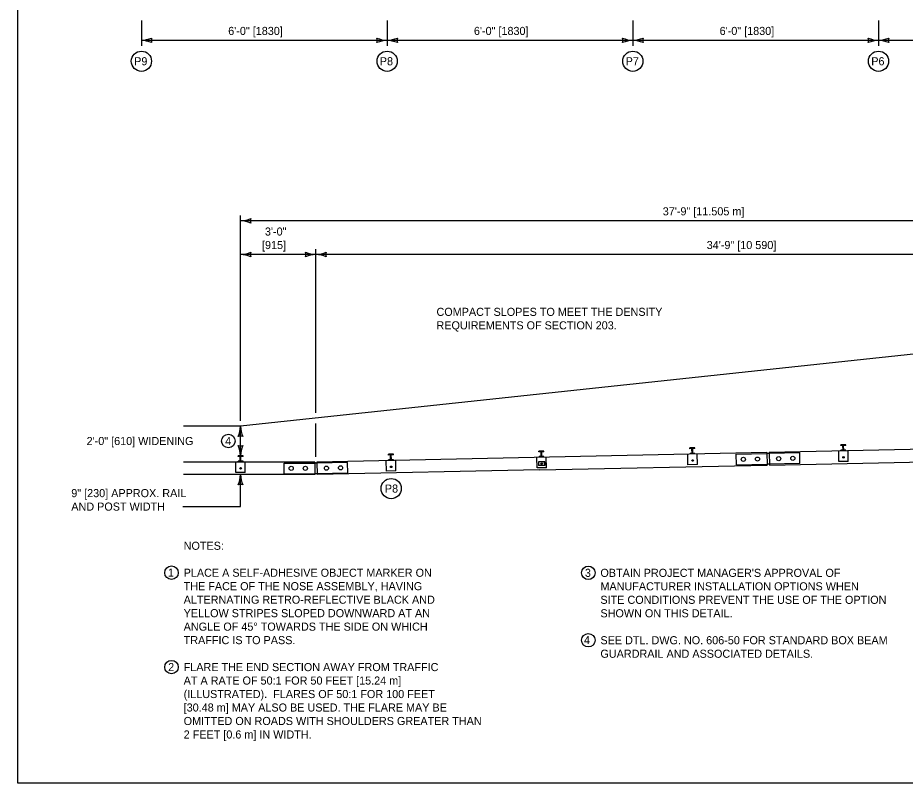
# Model space of a CAD drawing. Extents: x 49991.4 to 50021, y 49987.6 to 50011.4.
# Drawn here: x 49999.38 to 50005.97, y 49987.8 to 49993.48 of the extents above; entities that cross this region are included whole.
import ezdxf

# ---------------------------------------------------------------- set-up
doc = ezdxf.new("R2010")
doc.units = 0
for name, color, linetype in [('Level 1', 7, 'Continuous'), ('Level 2', 7, 'Continuous'), ('Level 3', 7, 'Continuous'), ('Level 4', 7, 'Continuous')]:
    doc.layers.add(name, color=color, linetype=linetype)

msp = doc.modelspace()

# ---------------------------------------------------------------- linework, layer by layer
at = {"layer": 'Level 1'}
for p, q in [((50008.0791, 49991.2004), (50001.0367, 49990.4473)), ((50001.0367, 49990.4473), (50000.6145, 49990.4473)), ((50004.4067, 49990.2872), (50004.3705, 49990.2864)), ((50004.3707, 49990.2808), (50004.3705, 49990.2864)), ((50004.386, 49990.2811), (50004.3707, 49990.2808)), ((50004.3867, 49990.2457), (50004.386, 49990.2811)), ((50004.4069, 49990.2816), (50004.3916, 49990.2812)), ((50004.3923, 49990.2458), (50004.3916, 49990.2812)), ((50004.4069, 49990.2816), (50004.4067, 49990.2872)), ((50008.3088, 49990.3226), (50004.9581, 49990.2521)), ((50005.5265, 49990.3107), (50005.4903, 49990.3099)), ((50005.4904, 49990.3043), (50005.4903, 49990.3099)), ((50005.5057, 49990.3047), (50005.4904, 49990.3043)), ((50005.5065, 49990.2693), (50005.5057, 49990.3047)), ((50005.5266, 49990.3051), (50005.5113, 49990.3048)), ((50005.5121, 49990.2694), (50005.5113, 49990.3048)), ((50005.5266, 49990.3051), (50005.5265, 49990.3107)), ((50001.0186, 49990.2226), (50001.0186, 49990.2283)), ((50001.0548, 49990.2283), (50001.0186, 49990.2283)), ((50001.0339, 49990.2226), (50001.0186, 49990.2226)), ((50001.0339, 49990.1873), (50001.0339, 49990.2226)), ((50001.0396, 49990.1873), (50001.0396, 49990.2226)), ((50001.0548, 49990.2226), (50001.0396, 49990.2226)), ((50001.0548, 49990.2226), (50001.0548, 49990.2283)), ((50004.9409, 49990.2518), (50001.6028, 49990.1816)), ((50002.1702, 49990.2403), (50002.1339, 49990.2395)), ((50002.1341, 49990.2338), (50002.1339, 49990.2395)), ((50002.1495, 49990.2341), (50002.1341, 49990.2338)), ((50002.1502, 49990.1988), (50002.1495, 49990.2341)), ((50002.1704, 49990.2346), (50002.1551, 49990.2342)), ((50002.1558, 49990.1989), (50002.1551, 49990.2342)), ((50002.1704, 49990.2346), (50002.1702, 49990.2403)), ((50003.2871, 49990.2636), (50003.2508, 49990.2629)), ((50003.2509, 49990.2573), (50003.2508, 49990.2629)), ((50003.2663, 49990.2576), (50003.2509, 49990.2573)), ((50003.267, 49990.2222), (50003.2516, 49990.2218)), ((50003.2518, 49990.2162), (50003.2516, 49990.2218)), ((50003.267, 49990.2222), (50003.2663, 49990.2576)), ((50003.2872, 49990.258), (50003.2718, 49990.2577)), ((50003.2725, 49990.2223), (50003.2718, 49990.2577)), ((50003.2879, 49990.2226), (50003.2725, 49990.2223)), ((50003.2872, 49990.258), (50003.2871, 49990.2636)), ((50003.288, 49990.217), (50003.2879, 49990.2226)), ((50004.3867, 49990.2457), (50004.3714, 49990.2454)), ((50004.3715, 49990.2398), (50004.3714, 49990.2454)), ((50004.4076, 49990.2462), (50004.3923, 49990.2458)), ((50004.4077, 49990.2405), (50004.4076, 49990.2462)), ((50004.9409, 49990.2517), (50004.9429, 49990.1587)), ((50004.9583, 49990.2453), (50004.941, 49990.2448)), ((50004.9581, 49990.2522), (50004.9601, 49990.159)), ((50005.5065, 49990.2693), (50005.4911, 49990.2689)), ((50005.4913, 49990.2633), (50005.4911, 49990.2689)), ((50005.5274, 49990.2697), (50005.5121, 49990.2694)), ((50005.5274, 49990.2641), (50005.5274, 49990.2697)), ((50001.5874, 49990.1817), (50000.6145, 49990.1817)), ((50001.0339, 49990.1873), (50001.0186, 49990.1873)), ((50001.0186, 49990.1817), (50001.0186, 49990.1873)), ((50001.0548, 49990.1873), (50001.0396, 49990.1873)), ((50001.0548, 49990.1817), (50001.0548, 49990.1873)), ((50001.5874, 49990.1816), (50001.5874, 49990.0885)), ((50001.6029, 49990.1747), (50001.5874, 49990.1747)), ((50001.6028, 49990.1816), (50001.6047, 49990.0884)), ((50002.1502, 49990.1988), (50002.1348, 49990.1985)), ((50002.1349, 49990.1929), (50002.1348, 49990.1985)), ((50002.171, 49990.1992), (50002.1558, 49990.1989)), ((50002.1712, 49990.1936), (50002.171, 49990.1992)), ((50003.2942, 49990.1843), (50003.2476, 49990.1833)), ((50003.2476, 49990.1833), (50003.2482, 49990.156)), ((50003.2947, 49990.157), (50003.2482, 49990.156)), ((50003.2903, 49990.1842), (50003.2908, 49990.1569)), ((50003.2942, 49990.1843), (50003.2947, 49990.157)), ((50004.9599, 49990.1659), (50004.9427, 49990.1655)), ((50001.5874, 49990.0885), (50000.6145, 49990.0885)), ((50001.6046, 49990.0953), (50001.5874, 49990.0953)), ((50003.2553, 49990.1231), (50001.6047, 49990.0884))]:
    msp.add_line(p, q, dxfattribs=at)
msp.add_lwpolyline([(49999.3835, 49998.9992), (50016.7501, 49998.9992), (50016.7501, 49987.7988), (49999.3835, 49987.7988)], close=True, dxfattribs=at)
for points in [[(50004.9601, 49990.1589), (50008.3108, 49990.2294)], [(50003.2538, 49990.1231), (50004.9429, 49990.1586)]]:
    msp.add_lwpolyline(points, dxfattribs=at)
for centre, radius in [((50004.7671, 49990.2015), 0.0153), ((50004.8719, 49990.2037), 0.0153), ((50005.0292, 49990.207), 0.0153), ((50005.134, 49990.2092), 0.0153), ((50005.5104, 49990.2171), 0.00582), ((50001.0369, 49990.1351), 0.00582), ((50001.4126, 49990.135), 0.0153), ((50001.5175, 49990.135), 0.0153), ((50001.6738, 49990.1365), 0.0153), ((50001.7786, 49990.1387), 0.0153), ((50002.1543, 49990.1466), 0.00582), ((50003.2712, 49990.1701), 0.00582), ((50004.3907, 49990.1936), 0.00582)]:
    msp.add_circle(centre, radius, dxfattribs=at)
at = {"layer": 'Level 2'}
for centre, radius in [((50000.301, 49993.1553), 0.075), ((50002.1241, 49993.1553), 0.075), ((50003.9471, 49993.1553), 0.075), ((50005.7702, 49993.1553), 0.075), ((50000.9464, 49990.3378), 0.05), ((50002.1543, 49989.985), 0.075), ((50000.5245, 49989.3607), 0.05), ((50003.6167, 49989.3598), 0.05), ((50003.6167, 49988.8598), 0.05), ((50000.5245, 49988.6607), 0.05)]:
    msp.add_circle(centre, radius, dxfattribs=at)
at = {"layer": 'Level 3'}
for p, q in [((50000.301, 49993.458), (50000.301, 49993.2703)), ((50002.124, 49993.458), (50002.124, 49993.2703)), ((50003.947, 49993.458), (50003.947, 49993.2703)), ((50005.7702, 49993.458), (50005.7702, 49993.2703)), ((50002.124, 49993.3103), (50000.301, 49993.3103)), ((50003.947, 49993.3103), (50002.124, 49993.3103)), ((50005.7702, 49993.3103), (50003.947, 49993.3103)), ((50007.5932, 49993.3103), (50005.7702, 49993.3103)), ((50001.0367, 49990.4873), (50001.0367, 49992.0119)), ((50008.0791, 49991.9719), (50001.0367, 49991.9719)), ((50001.5952, 49991.7219), (50001.0367, 49991.7219)), ((50001.5952, 49990.547), (50001.5952, 49991.7619)), ((50008.0791, 49991.7219), (50001.5952, 49991.7219)), ((50001.0364, 49990.2283), (50001.0364, 49990.4473)), ((50001.5952, 49990.2217), (50001.5952, 49990.467)), ((50001.0364, 49989.8513), (50001.0364, 49990.0885)), ((50000.6089, 49989.8513), (50001.0364, 49989.8513))]:
    msp.add_line(p, q, dxfattribs=at)
for centre, radius, start, end in [((50000.2895, 49993.543), 0.233, 272.82731, 292.07716), ((50000.2918, 49993.0882), 0.2223, 67.45601, 87.63952), ((50000.4292, 49993.3103), 0.0548, 162.13882, 197.86118), ((50002.1332, 49993.5324), 0.2223, 247.45601, 267.63952), ((50001.9958, 49993.3103), 0.0548, 342.13882, 17.86118), ((50002.1355, 49993.0776), 0.233, 92.82731, 112.07716), ((50002.1125, 49993.543), 0.233, 272.82731, 292.07716), ((50002.1148, 49993.0882), 0.2223, 67.45601, 87.63952), ((50002.2522, 49993.3103), 0.0548, 162.13882, 197.86118), ((50003.9562, 49993.5324), 0.2223, 247.45601, 267.63952), ((50003.8188, 49993.3103), 0.0548, 342.13882, 17.86118), ((50003.9585, 49993.0776), 0.233, 92.82731, 112.07716), ((50003.9355, 49993.543), 0.233, 272.82731, 292.07716), ((50003.9378, 49993.0882), 0.2223, 67.45601, 87.63952), ((50004.0752, 49993.3103), 0.0548, 162.13882, 197.86118), ((50005.7794, 49993.5324), 0.2223, 247.45601, 267.63952), ((50005.642, 49993.3103), 0.0548, 342.13882, 17.86118), ((50005.7817, 49993.0776), 0.233, 92.82731, 112.07716), ((50005.7587, 49993.543), 0.233, 272.82731, 292.07716), ((50005.761, 49993.0882), 0.2223, 67.45601, 87.63952), ((50005.8984, 49993.3103), 0.0548, 162.13882, 197.86118), ((50001.0252, 49992.2046), 0.233, 272.82731, 292.07716), ((50001.1649, 49991.9719), 0.0548, 162.13882, 197.86118), ((50001.0275, 49991.7498), 0.2223, 67.45601, 87.63952), ((50001.0252, 49991.9546), 0.233, 272.82731, 292.07716), ((50001.0275, 49991.4998), 0.2223, 67.45601, 87.63952), ((50001.1649, 49991.7219), 0.0548, 162.13882, 197.86118), ((50001.6043, 49991.944), 0.2223, 247.45601, 267.63952), ((50001.467, 49991.7219), 0.0548, 342.13882, 17.86118), ((50001.6067, 49991.4892), 0.233, 92.82731, 112.07716), ((50001.7243, 49991.7219), 0.0548, 162.13882, 197.86118), ((50000.8143, 49990.4565), 0.2223, 337.45601, 357.63952), ((50001.2691, 49990.4588), 0.233, 182.82731, 202.07716), ((50001.0364, 49990.3191), 0.0548, 72.13882, 107.86118), ((50001.0364, 49990.3565), 0.0548, 252.13882, 287.86118), ((50000.8037, 49990.2168), 0.233, 2.82731, 22.07716), ((50001.2585, 49990.2191), 0.2223, 157.45601, 177.63952), ((50000.8143, 49990.0977), 0.2223, 337.45601, 357.63952), ((50001.2691, 49990.1), 0.233, 182.82731, 202.07716), ((50001.0364, 49989.9603), 0.0548, 72.13882, 107.86118)]:
    msp.add_arc(centre, radius, start, end, dxfattribs=at)
for centre, major_axis, start_param, end_param in [((50001.5835, 49991.9546), (0.2358, 0), 4.761735, 5.097708), ((50001.5859, 49991.4998), (0.225, 0), 1.177329, 1.529598)]:
    msp.add_ellipse(centre, major_axis=major_axis, ratio=0.987928, start_param=start_param, end_param=end_param, dxfattribs=at)
at = {"layer": 'Level 4'}
for p, q in [((50003.2366, 49990.1382), (50003.235, 49990.2159)), ((50003.3066, 49990.1397), (50003.3049, 49990.2173)), ((50004.3563, 49990.1618), (50004.3546, 49990.2395)), ((50004.4261, 49990.1633), (50004.4245, 49990.2409)), ((50004.7137, 49990.2401), (50004.941, 49990.2448)), ((50004.7154, 49990.1607), (50004.7137, 49990.2401)), ((50005.1856, 49990.2501), (50004.9583, 49990.2453)), ((50005.1873, 49990.1706), (50005.1856, 49990.2501)), ((50005.476, 49990.1853), (50005.4744, 49990.263)), ((50005.5459, 49990.1868), (50005.5442, 49990.2644)), ((50001.0017, 49990.1039), (50001.0017, 49990.1817)), ((50001.0716, 49990.1039), (50001.0716, 49990.1817)), ((50001.3601, 49990.0953), (50001.3601, 49990.1747)), ((50001.3601, 49990.1747), (50001.5874, 49990.1747)), ((50001.8302, 49990.1795), (50001.6028, 49990.1747)), ((50001.8318, 49990.1001), (50001.8302, 49990.1795)), ((50002.1198, 49990.1148), (50002.1181, 49990.1926)), ((50002.1896, 49990.1162), (50002.188, 49990.194)), ((50004.4261, 49990.1633), (50004.3563, 49990.1618)), ((50004.7154, 49990.1607), (50004.9427, 49990.1655)), ((50005.1873, 49990.1706), (50004.9599, 49990.1659)), ((50005.5459, 49990.1868), (50005.476, 49990.1853)), ((50001.0716, 49990.1039), (50001.0017, 49990.1039)), ((50001.3601, 49990.0953), (50001.5874, 49990.0953)), ((50001.8318, 49990.1001), (50001.6045, 49990.0953)), ((50002.1896, 49990.1162), (50002.1198, 49990.1148)), ((50003.3066, 49990.1397), (50003.2366, 49990.1382))]:
    msp.add_line(p, q, dxfattribs=at)

# ---------------------------------------------------------------- texts
at = {"layer": 'Level 2'}
for s, p in [('6\'-0" [1830]', (50000.945, 49993.3503)), ('6\'-0" [1830]', (50002.768, 49993.3503)), ('6\'-0" [1830]', (50004.5911, 49993.3503)), ('P9', (50000.2471, 49993.1253)), ('P8', (50002.0697, 49993.1253)), ('P7', (50003.8939, 49993.1253)), ('P6', (50005.7163, 49993.1253)), ('37\'-9" [11.505 m]', (50004.1691, 49992.0119)), ('3\'-0"', (50001.2175, 49991.8619)), ('[915]', (50001.1957, 49991.7619)), ('34\'-9" [10 590]', (50004.4952, 49991.7619)), ('COMPACT SLOPES TO MEET THE DENSITY', (50002.4903, 49991.2661)), ('REQUIREMENTS OF SECTION 203.', (50002.4903, 49991.1661)), ('2\'-0" [610] WIDENING', (49999.8943, 49990.3079)), ('4', (50000.9224, 49990.3078)), ('P8', (50002.1074, 49989.955)), ('9" [230] APPROX. RAIL ', (49999.7807, 49989.9213)), ('AND POST WIDTH', (49999.7807, 49989.8213)), ('NOTES:', (50000.6145, 49989.5307)), ('1', (50000.4982, 49989.3317)), ('PLACE A SELF-ADHESIVE OBJECT MARKER ON', (50000.6145, 49989.3307)), ('3', (50003.5915, 49989.3298)), ("OBTAIN PROJECT MANAGER'S APPROVAL OF", (50003.7067, 49989.3298)), ('THE FACE OF THE NOSE ASSEMBLY, HAVING', (50000.6145, 49989.2307)), ('MANUFACTURER INSTALLATION OPTIONS WHEN', (50003.7067, 49989.2298)), ('ALTERNATING RETRO-REFLECTIVE BLACK AND', (50000.6145, 49989.1307)), ('SITE CONDITIONS PREVENT THE USE OF THE OPTION ', (50003.7067, 49989.1298)), ('YELLOW STRIPES SLOPED DOWNWARD AT AN', (50000.6145, 49989.0307)), ('SHOWN ON THIS DETAIL.', (50003.7067, 49989.0298)), ('ANGLE OF 45° TOWARDS THE SIDE ON WHICH', (50000.6145, 49988.9307)), ('TRAFFIC IS TO PASS.', (50000.6145, 49988.8307)), ('4', (50003.5849, 49988.8315)), ('SEE DTL. DWG. NO. 606-50 FOR STANDARD BOX BEAM', (50003.7067, 49988.8298)), ('GUARDRAIL AND ASSOCIATED DETAILS.', (50003.7067, 49988.7298)), ('2', (50000.4993, 49988.6307)), ('FLARE THE END SECTION AWAY FROM TRAFFIC', (50000.6145, 49988.6307)), ('AT A RATE OF 50:1 FOR 50 FEET [15.24 m]', (50000.6145, 49988.5307)), ('(ILLUSTRATED).  FLARES OF 50:1 FOR 100 FEET', (50000.6145, 49988.4307)), ('[30.48 m] MAY ALSO BE USED. THE FLARE MAY BE', (50000.6145, 49988.3307)), ('OMITTED ON ROADS WITH SHOULDERS GREATER THAN', (50000.6145, 49988.2307)), ('2 FEET [0.6 m] IN WIDTH.', (50000.6145, 49988.1307))]:
    msp.add_text(s, height=0.06, dxfattribs=at).set_placement(p)

doc.saveas('drawing.dxf')
